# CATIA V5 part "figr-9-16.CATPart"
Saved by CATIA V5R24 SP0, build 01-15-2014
Part number: Part1
Bounding box of the stored display mesh (mm): x -77.304 to 77.304, y -77.304 to 125.507, z 0 to 125
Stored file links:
  D:\KAVITA\CATIA V5-6R2014 Project_ Kavita\CATIA V5-6R2014_partfiles\Partfiles\c09_catia_v5-6r2014_prt\figr-9-16.CATPart
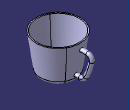
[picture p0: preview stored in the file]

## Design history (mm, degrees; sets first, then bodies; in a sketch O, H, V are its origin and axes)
Set1
  Plane1: type Normal, Curve Sketch3, RefPoint vertex of Sketch3
Body1 (main body)
  Sketch1 on yz-plane, origin (0, 0, 0), H (0, 1, 0), V (0, 0, 1)
    line L1 (0, 0) -> (60, 0)
    point P1 (60, 0)
    point P2 (60, 0)
    line L2 (60, 0) -> (77.5, 125)
    point P3 (77.5, 125)
    line L3 (77.5, 125) -> (0, 125)
    point P4 (0, 125)
    line L4 (0, 125) -> (0, 0)
    axis line L5 (0, 150.2858) -> (0, -31.0593)
    point P5 (0, 150.2858)
    radius about axis P1 L5 = 60
    radius about axis P3 L5 = 77.5
    distance L3 L1 = 125
    horizontal: L1 H, L3 H
    coincidence: P4 V, P2 P1, P5 V
    vertical: L4 V, L5 V
  Shaft1: profile Sketch1, axis Sketch1.L5, angle 360
  Fillet1: radius 15, on edge [face of Shaft1 | face of Shaft1]
  Shell1: ExtOffset 0, Face face of Shaft1, IntOffset 4
  Sketch2 on Plane1, origin (0, 62.9841, 0), H (-1, 0, 0), V (0, 0, 1)
    circle A1 centre (0, 22.002) radius 7.5
    reference projected point E1 (0, 22.002) from vertex of Sketch3
    radius A1 = 7.5
    concentricity: A1 E1
  Sketch3 on yz-plane, origin (0, 0, 0), H (0, 1, 0), V (0, 0, 1)
    line L1 (62.9841, 22.002) -> (78.2172, 22.002)
    arc A1 centre (78.2172, 44.1133) radius 22.1113 from (78.2172, 22.002) to (97.9307, 34.0988) ccw
    arc A2 centre (-112.3295, 140.9107) radius 235.8349 from (97.9307, 34.0988) to (117.8681, 89.6549) ccw
    arc A3 centre (104.0328, 92.7355) radius 14.1742 from (117.8681, 89.6549) to (104.4272, 106.9041) ccw
    arc A4 centre (93.6744, -279.4123) radius 386.4661 from (104.4272, 106.9041) to (82.9216, 106.9041) ccw
    horizontal: L1 H
    tangency: A1 L1, A2 A1, A3 A2, A4 A3
  Rib1: profile Sketch2, centre curve Sketch3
